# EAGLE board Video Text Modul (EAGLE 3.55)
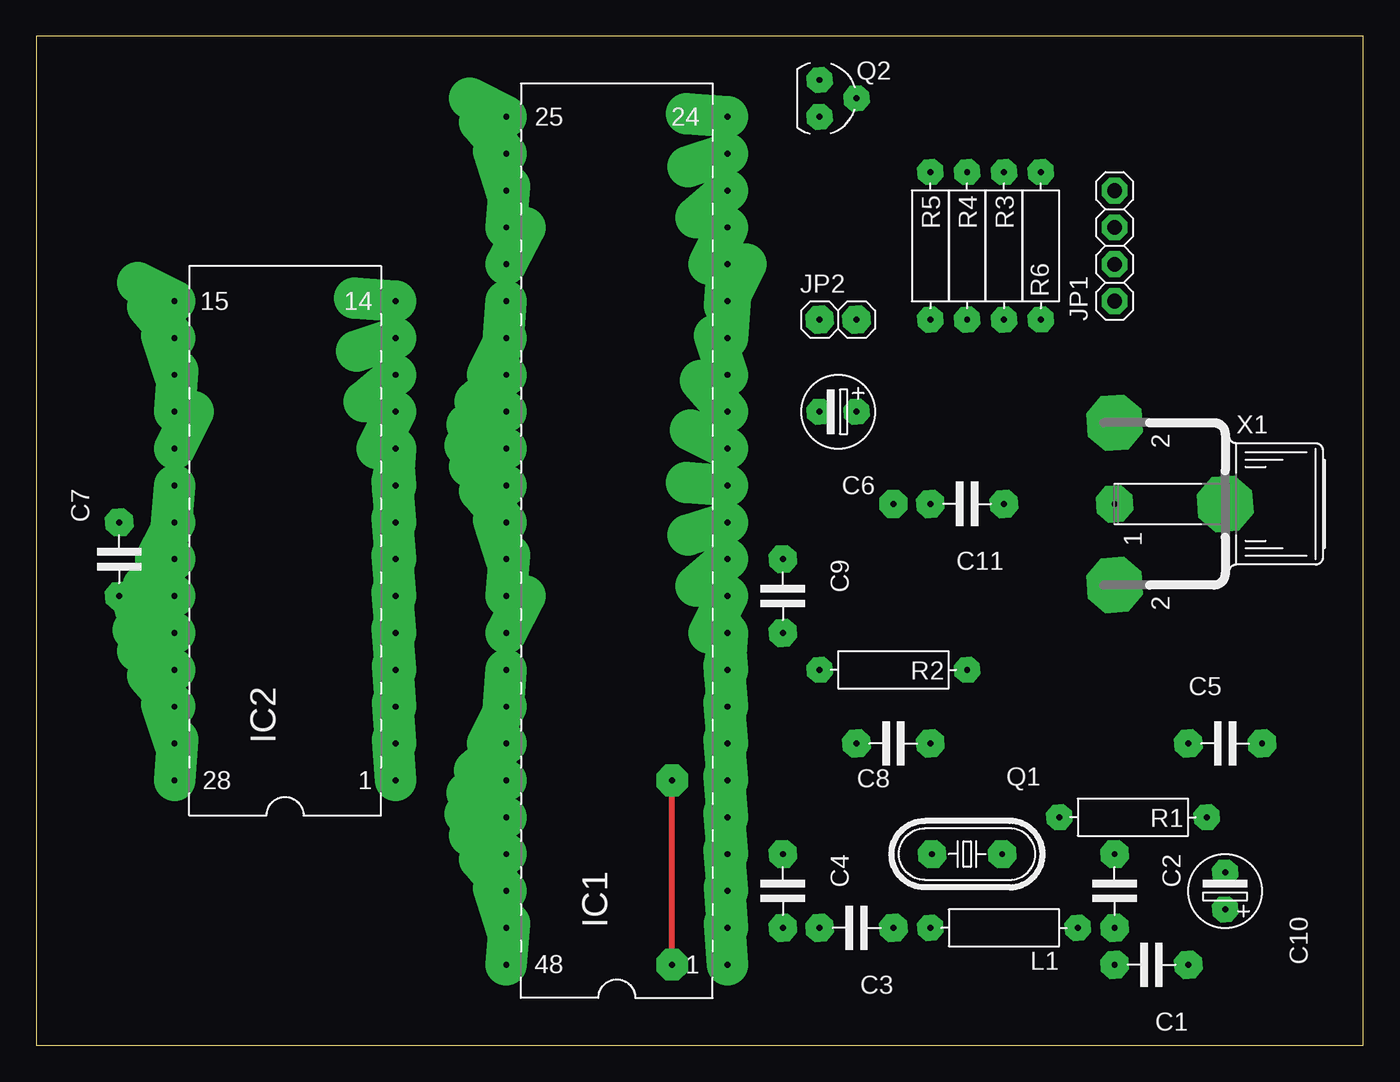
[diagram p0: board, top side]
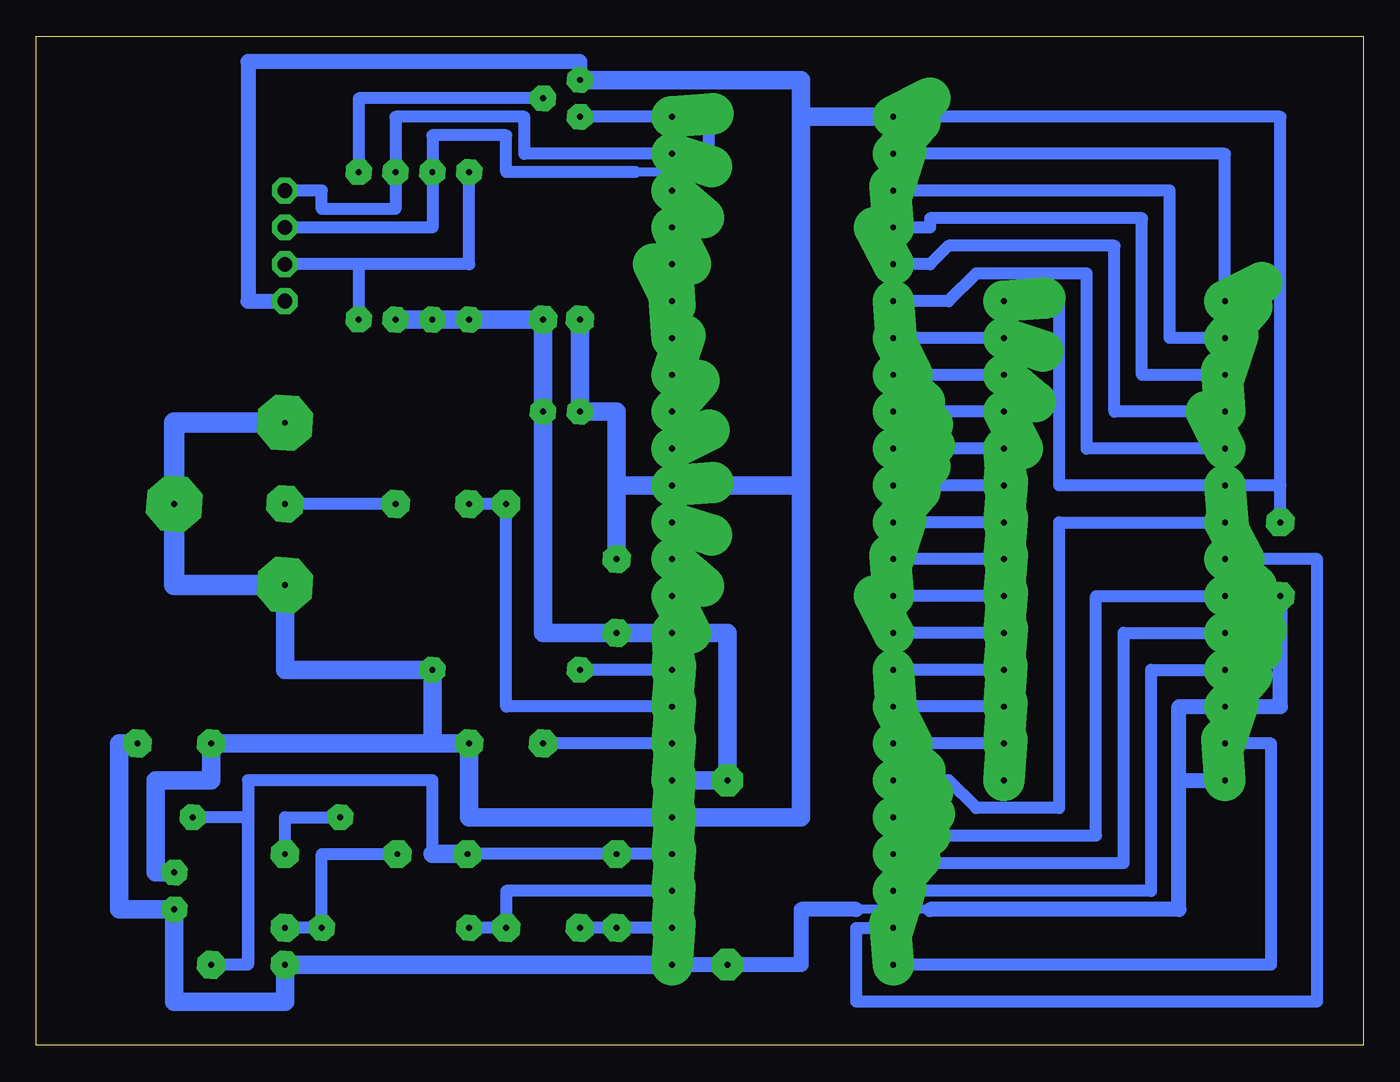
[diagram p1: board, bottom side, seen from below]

Size 91.42 x 69.52 mm. Coordinates in mm from the lower left corner, seen from the top.
Outline: 0,0 91.42,0 91.42,69.52 0,69.52 0,0
Copper layers used: Top, Bottom

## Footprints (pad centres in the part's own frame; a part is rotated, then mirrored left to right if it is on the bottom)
5 = drill 0.406 pad 1.93 octagon:  -2.54,0;  2.54,0
-2,5L = drill 0.406 pad 1.778 octagon:  0,0;  2.54,0
L48 = drill 0.406 pad 2.845 offset:  -29.21,-7.62;  -26.67,-7.62;  -24.13,-7.62;  -21.59,-7.62;  -19.05,-7.62;  -16.51,-7.62;  -13.97,-7.62;  -11.43,-7.62;  -8.89,-7.62;  -6.35,-7.62;  -3.81,-7.62;  -1.27,-7.62;  1.27,-7.62;  3.81,-7.62;  6.35,-7.62;  8.89,-7.62;  11.43,-7.62;  13.97,-7.62;  16.51,-7.62;  19.05,-7.62;  21.59,-7.62;  24.13,-7.62;  26.67,-7.62;  29.21,-7.62;  29.21,7.62;  26.67,7.62;  24.13,7.62;  21.59,7.62;  19.05,7.62;  16.51,7.62;  13.97,7.62;  11.43,7.62;  8.89,7.62;  6.35,7.62;  3.81,7.62;  1.27,7.62;  -1.27,7.62;  -3.81,7.62;  -6.35,7.62;  -8.89,7.62;  -11.43,7.62;  -13.97,7.62;  -16.51,7.62;  -19.05,7.62;  -21.59,7.62;  -24.13,7.62;  -26.67,7.62;  -29.21,7.62
L28-6 = drill 0.406 pad 2.845 offset:  -16.51,-7.62;  -13.97,-7.62;  -11.43,-7.62;  -8.89,-7.62;  -6.35,-7.62;  -3.81,-7.62;  -1.27,-7.62;  1.27,-7.62;  3.81,-7.62;  6.35,-7.62;  8.89,-7.62;  11.43,-7.62;  13.97,-7.62;  16.51,-7.62;  16.51,7.62;  13.97,7.62;  11.43,7.62;  8.89,7.62;  6.35,7.62;  3.81,7.62;  1.27,7.62;  -1.27,7.62;  -3.81,7.62;  -6.35,7.62;  -8.89,7.62;  -11.43,7.62;  -13.97,7.62;  -16.51,7.62
04 = drill 1.016 pad 1.6 octagon:  -3.81,0;  -1.27,0;  1.27,0;  3.81,0
2 = drill 0.406 pad 1.93 octagon:  -1.27,0;  1.27,0
10 = drill 0.406 pad 1.778 octagon:  -5.08,0;  5.08,0
8U-V = drill 0.406 pad 1.93 octagon:  -2.413,0;  2.413,0
-92C = drill 0.406 pad 1.778 octagon:  0,-1.27;  2.54,0;  0,1.27
BU3 = drill 0.406 pad 2.54 octagon:  0,-2.54 | drill 0.406 pad 3.81 octagon:  5.588,-2.54;  -5.588,-2.54;  0,5.08

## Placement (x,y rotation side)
C1  100n  [5]  76.83,5.55 180 top
C2  1n  [5]  74.29,10.63 270 top
C3  10p  [5]  56.51,8.09 180 top
C4  15p  [5]  51.43,10.63 270 top
C5  100n  [5]  81.91,20.79 0 top
C6  100æ  [-2,5L]  56.51,43.65 180 top
C7  100n  [5]  5.71,33.49 270 top
C8  100n  [5]  59.05,20.79 0 top
C9  100n  [5]  51.43,30.95 270 top
C10  10æ  [-2,5L]  81.91,9.36 90 top
C11  100n  [5]  64.13,37.3 180 top
IC1  SAA5246  [L48]  40,34.76 90 top
IC2  6264A  [L28-6]  17.14,34.76 90 top
JP1  Centr  [04]  74.29,55.08 90 top
JP2  Game  [2]  55.24,50 0 top
L1  4,7æH  [10]  66.67,8.09 180 top
Q1  27Mhz  [8U-V]  64.13,13.17 180 top
Q2  BC548B  [-92C]  53.97,65.24 0 top
R1  3,3k  [10]  75.56,15.71 180 top
R2  27k  [10]  59.05,25.87 180 top
R3  10k  [10]  66.67,55.08 270 top
R4  10k  [10]  64.13,55.08 270 top
R5  10k  [10]  61.59,55.08 270 top
R6  10k  [10]  69.21,55.08 90 top
X1  FBAS  [BU3]  76.83,37.3 270 top

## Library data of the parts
C1-C5 C7-C9 C11 IC1 JP2 L1 Q1 Q2 X1 = eigene
C6 C10 R1-R6 = DISCRETE
IC2 = DIL-E
JP1 = PINHEAD

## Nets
+5V: C1. C5. C6. C7. C9. C10. IC1. IC2. JP2. R3. R4. R5.
D0: IC1. IC2.
D1: IC1. IC2.
D2: IC1. IC2.
D3: IC1. IC2.
D4: IC1. IC2.
D5: IC1. IC2.
D6: IC1. IC2.
D7: IC1. IC2.
GND: C5. C6. C7. C8. C9. C10. IC1. IC2. JP1. JP2. Q2. R2. X1.
N$1: C3. C4. IC1.
N$2: C3. IC1. L1.
N$3: C2. L1. Q1.
N$4: IC1. IC2.
N$5: C1. C4. IC1. Q1. R1.
N$6: IC1. R2.
N$7: C8. IC1.
N$8: C11. X1.
N$9: C2. R1.
N$10: C11. IC1.
N$11: IC1. JP1. R3.
N$12: IC1. IC2.
N$14: IC1. JP1. Q2. R4.
N$16: IC1. IC2.
N$17: IC1. IC2.
N$18: IC1. IC2.
N$19: IC1. IC2.
N$20: IC1. IC2.
N$21: IC1. IC2.
N$22: IC1. IC2.
N$23: IC1. IC2.
N$24: IC1. IC2.
N$25: IC1. IC2.
N$26: IC1. IC2.
N$27: IC1. IC2.
N$28: IC1. IC2.
N$30: Q2. R6.
N$31: JP1. R5. R6.

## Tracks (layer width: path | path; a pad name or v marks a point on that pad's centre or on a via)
+5V  (via drill 0.41 pad 2.18)
  Top 0.406: v43.81,5.55 v43.81,18.25
  Bottom 0.61: 29.84,9.36 34.92,9.36
  Bottom 1.016: 12.7,18.25 12.7,23.33 9.52,23.33 5.71,23.33 C7. | 12.7,18.25 IC2. | 12.7,18.25 12.7,9.36 29.84,9.36 | 34.92,9.36 38.73,9.36 38.73,5.55 v43.81,5.55 47.62,5.55
  Bottom 1.27: 47.62,28.41 C9. | C9. 56.51,28.41 56.51,43.65 | 56.51,43.65 JP2. | JP2. R5. R4. R3. | 47.62,18.25 v43.81,18.25 43.81,28.41 47.62,28.41 | 47.62,5.55 C1. 74.29,3.01 81.91,3.01 81.91,9.36 85.72,9.36 85.72,20.79 C5. | 47.62,28.41 C9. | 56.51,43.65 JP2.
D0
  Bottom 0.813: 32.38,61.43 9.52,61.43 9.52,51.27
D1
  Bottom 0.813: 9.52,48.73 13.33,48.73 13.33,58.89 32.38,58.89
D2
  Bottom 0.813: 32.38,56.35 29.84,56.35 29.84,56.98 15.23,56.98 15.23,46.19 9.52,46.19
D3
  Bottom 0.813: 9.52,43.65 17.14,43.65 17.14,55.08 28.57,55.08 29.84,53.81 32.38,53.81
D4
  Bottom 0.813: 32.38,51.27 28.57,51.27 26.66,53.18 19.04,53.18 19.04,41.11 9.52,41.11
D5
  Bottom 0.813: 24.76,48.73 32.38,48.73
D6
  Bottom 0.813: 24.76,46.19 32.38,46.19
D7
  Bottom 0.813: 24.76,43.65 32.38,43.65
GND
  Bottom 0.813: 24.76,51.27 20.95,51.27 20.95,38.57 9.52,38.57 5.71,38.57 | 32.38,63.97 5.71,63.97 5.71,38.57 | 5.71,36.03 5.71,38.57
  Bottom 1.016: 74.29,51.27 76.83,51.27 76.83,67.78 53.97,67.78 Q2.
  Bottom 1.27: 38.73,38.57 47.62,38.57 51.43,38.57 51.43,33.49 51.43,43.65 C6. 53.97,50 | 38.73,63.97 38.73,38.57 | 32.38,63.97 38.73,63.97 | 64.13,20.79 C8. 61.59,15.71 47.62,15.71 38.73,15.71 38.73,38.57 | 64.13,20.79 64.13,25.87 74.29,25.87 74.29,31.71 | C10. 83.18,11.9 83.18,18.25 79.37,18.25 79.37,20.79 64.13,20.79 | Q2. 38.73,66.51 38.73,63.97
  Bottom 1.422: 74.29,31.71 81.91,31.71 X1. 81.91,42.89 74.29,42.89
N$1
  Bottom 0.813: 47.62,8.09 C4. C3.
N$2
  Bottom 0.813: 47.62,10.63 59.05,10.63 59.05,8.09 L1.
N$3
  Bottom 0.813: C2. 71.75,8.09 71.75,13.17 66.54,13.17
N$4
  Bottom 0.813: IC1. 6.35,5.55 6.35,20.79 9.52,20.79
N$5
  Bottom 0.813: 47.62,13.17 51.43,13.17 64.13,13.17 64.13,18.25 76.83,18.25 76.83,5.55 | 76.83,5.55 76.83,15.71 80.64,15.71 | 76.83,5.55 79.37,5.55
  Bottom 1.27: 64.13,13.17 Q1.
N$6
  Bottom 0.813: 47.62,25.87 R2.
N$7
  Bottom 0.813: 47.62,20.79 56.51,20.79
N$8
  Bottom 0.813: 66.67,37.3 74.29,37.3
N$9
  Bottom 0.813: 74.29,13.17 74.29,15.71 R1.
N$10  (via drill 0.41 pad 1.93)
  Bottom 0.813: C11. v59.05,37.3 59.05,23.33 47.62,23.33
N$11
  Bottom 0.813: 47.62,61.43 57.78,61.43 57.78,63.97 66.67,63.97 66.67,60.16 66.67,57.62 71.75,57.62 71.75,58.89 JP1.
N$12
  Bottom 0.813: 9.52,33.49 3.17,33.49 3.17,3.01 34.92,3.01 34.92,8.09 32.38,8.09
N$13  (via drill 0.41 pad 1.78)
  other vias: 74.29,58.89
N$14
  Bottom 0.61: 45.08,60.16 50.16,60.16
  Bottom 0.813: 53.97,63.97 47.62,63.97 45.08,63.97 45.08,60.16 | 50.16,60.16 59.05,60.16 59.05,62.7 64.13,62.7 64.13,60.16 64.13,56.35 74.29,56.35
N$15  (via drill 0.41 pad 1.78)
  other vias: 74.29,56.35
N$16
  Bottom 0.813: 24.76,41.11 32.38,41.11
N$17
  Bottom 0.813: 24.76,38.57 32.38,38.57
N$18
  Bottom 0.813: 24.76,36.03 32.38,36.03
N$19
  Bottom 0.813: 24.76,33.49 32.38,33.49
N$20
  Bottom 0.813: 24.76,30.95 32.38,30.95
N$21
  Bottom 0.813: 24.76,28.41 32.38,28.41
N$22
  Bottom 0.813: 24.76,25.87 32.38,25.87
N$23
  Bottom 0.813: 24.76,23.33 32.38,23.33
N$24
  Bottom 0.813: 24.76,20.79 32.38,20.79
N$25
  Bottom 0.813: 9.52,36.03 20.95,36.03 20.95,16.34 26.66,16.34 28.57,18.25 32.38,18.25
N$26
  Bottom 0.813: 32.38,15.71 30.47,15.71 29.2,14.44 18.41,14.44 18.41,30.95 9.52,30.95
N$27
  Bottom 0.813: 32.38,13.17 30.47,13.17 29.84,12.54 16.5,12.54 16.5,28.41 9.52,28.41
N$28
  Bottom 0.813: 9.52,25.87 14.6,25.87 14.6,10.63 32.38,10.63
N$29  (via drill 0.41 pad 1.78)
  other vias: 74.29,53.81
N$30
  Bottom 0.813: 56.51,65.24 69.21,65.24 R6.
N$31
  Bottom 0.813: 69.21,53.81 74.29,53.81 | 69.21,53.81 69.21,50 | 61.59,60.16 61.59,53.81 69.21,53.81
N$32  (via drill 0.41 pad 1.78)
  other vias: 74.29,51.27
